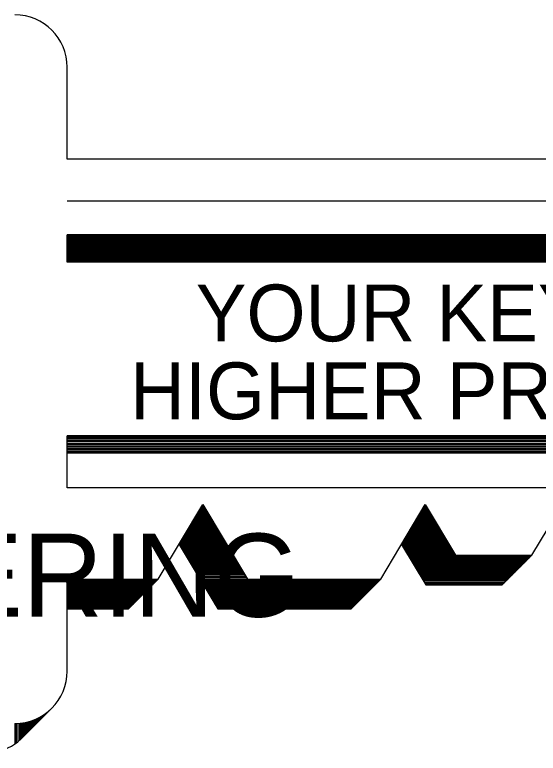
# Model space of a CAD drawing. Extents: x 44743.44 to 44747.1, y 44738.46 to 44741.29.
# Drawn here: x 44743.6828 to 44743.7348, y 44738.5496 to 44738.6229 of the extents above; entities that cross this region are included whole.
import ezdxf

# ---------------------------------------------------------------- set-up
doc = ezdxf.new("R2010")
doc.units = 0
for name, color, linetype in [('Level 1', 7, 'Continuous'), ('Level 10', 7, 'Continuous'), ('Level 2', 7, 'Continuous'), ('Level 7', 7, 'Continuous')]:
    doc.layers.add(name, color=color, linetype=linetype)

msp = doc.modelspace()

# ---------------------------------------------------------------- linework, layer by layer
at = {"layer": 'Level 1'}
msp.add_line((44743.6880458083, 44738.598307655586), (44743.6880458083, 44738.60102640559), dxfattribs=at)
at = {"layer": 'Level 10'}
msp.add_line((44743.7781708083, 44738.60438057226), (44743.6880458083, 44738.60438057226), dxfattribs=at)
at = {"layer": 'Level 2'}
for p, q in [((44743.782222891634, 44738.60102640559), (44743.6880458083, 44738.60102640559)), ((44743.782306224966, 44738.60096390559), (44743.6880458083, 44738.60096390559)), ((44743.78237914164, 44738.60090140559), (44743.6880458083, 44738.60090140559)), ((44743.78246247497, 44738.600828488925), (44743.6880458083, 44738.600828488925)), ((44743.78255622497, 44738.60075557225), (44743.6880458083, 44738.60075557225)), ((44743.7826395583, 44738.60068265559), (44743.6880458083, 44738.60068265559)), ((44743.782743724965, 44738.60059932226), (44743.6880458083, 44738.60059932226)), ((44743.7828270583, 44738.600526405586), (44743.6880458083, 44738.600526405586)), ((44743.78293122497, 44738.60044307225), (44743.6880458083, 44738.60044307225)), ((44743.783035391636, 44738.60035973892), (44743.6880458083, 44738.60035973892)), ((44743.78311872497, 44738.60028682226), (44743.6880458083, 44738.60028682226)), ((44743.78321247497, 44738.600203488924), (44743.6880458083, 44738.600203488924)), ((44743.7833270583, 44738.60012015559), (44743.6880458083, 44738.60012015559)), ((44743.78341039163, 44738.60004723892), (44743.6880458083, 44738.60004723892)), ((44743.783493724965, 44738.59997432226), (44743.6880458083, 44738.59997432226)), ((44743.783597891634, 44738.599890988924), (44743.6880458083, 44738.599890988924)), ((44743.7837020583, 44738.59980765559), (44743.6880458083, 44738.59980765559)), ((44743.783795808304, 44738.59972432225), (44743.6880458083, 44738.59972432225)), ((44743.783910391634, 44738.59963057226), (44743.6880458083, 44738.59963057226)), ((44743.784004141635, 44738.59955765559), (44743.6880458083, 44738.59955765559)), ((44743.784097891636, 44738.599474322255), (44743.6880458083, 44738.599474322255)), ((44743.784212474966, 44738.599380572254), (44743.6880458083, 44738.599380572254)), ((44743.784316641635, 44738.59929723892), (44743.6880458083, 44738.59929723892)), ((44743.7843895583, 44738.59923473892), (44743.6880458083, 44738.59923473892)), ((44743.78449372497, 44738.599151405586), (44743.6880458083, 44738.599151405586)), ((44743.78458747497, 44738.59906807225), (44743.6880458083, 44738.59906807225)), ((44743.78468122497, 44738.59899515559), (44743.6880458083, 44738.59899515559)), ((44743.7847645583, 44738.598922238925), (44743.6880458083, 44738.598922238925)), ((44743.784847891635, 44738.59885973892), (44743.6880458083, 44738.59885973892)), ((44743.784962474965, 44738.59876598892), (44743.6880458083, 44738.59876598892)), ((44743.78503539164, 44738.59870348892), (44743.6880458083, 44738.59870348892)), ((44743.78511872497, 44738.598630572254), (44743.6880458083, 44738.598630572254)), ((44743.78519164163, 44738.59856807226), (44743.6880458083, 44738.59856807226)), ((44743.785274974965, 44738.598505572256), (44743.6880458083, 44738.598505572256)), ((44743.78533747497, 44738.59845348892), (44743.6880458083, 44738.59845348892)), ((44743.78541039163, 44738.598390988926), (44743.6880458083, 44738.598390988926)), ((44743.78546247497, 44738.59834932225), (44743.6880458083, 44738.59834932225)), ((44743.7855145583, 44738.598307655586), (44743.6880458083, 44738.598307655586)), ((44743.790337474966, 44738.581099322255), (44743.6880458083, 44738.581099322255)), ((44743.6880458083, 44738.575932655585), (44743.6880458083, 44738.581099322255)), ((44743.7901708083, 44738.58096390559), (44743.6880458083, 44738.58096390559)), ((44743.78999372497, 44738.58081807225), (44743.6880458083, 44738.58081807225)), ((44743.7897958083, 44738.58065140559), (44743.6880458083, 44738.58065140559)), ((44743.78962914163, 44738.58051598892), (44743.6880458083, 44738.58051598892)), ((44743.78943122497, 44738.580349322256), (44743.6880458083, 44738.580349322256)), ((44743.78925414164, 44738.58020348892), (44743.6880458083, 44738.58020348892)), ((44743.789066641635, 44738.580047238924), (44743.6880458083, 44738.580047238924)), ((44743.788858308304, 44738.57988057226), (44743.6880458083, 44738.57988057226)), ((44743.7886708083, 44738.579724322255), (44743.6880458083, 44738.579724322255)), ((44743.78849372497, 44738.57957848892), (44743.6880458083, 44738.57957848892)), ((44743.78836872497, 44738.57947432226), (44743.6880458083, 44738.57947432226)), ((44743.78825414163, 44738.57938057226), (44743.6880458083, 44738.57938057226)), ((44743.78408747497, 44738.575932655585), (44743.6880458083, 44738.575932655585)), ((44743.701243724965, 44738.57382848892), (44743.701764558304, 44738.57382848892)), ((44743.7012958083, 44738.573911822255), (44743.70171247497, 44738.573911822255)), ((44743.701337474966, 44738.57399515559), (44743.7016708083, 44738.57399515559)), ((44743.7013895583, 44738.57407848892), (44743.70161872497, 44738.57407848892)), ((44743.701441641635, 44738.57416182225), (44743.701566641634, 44738.57416182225)), ((44743.723306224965, 44738.57382848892), (44743.723827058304, 44738.57382848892)), ((44743.7233583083, 44738.573911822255), (44743.72377497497, 44738.573911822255)), ((44743.723399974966, 44738.57399515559), (44743.7237333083, 44738.57399515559)), ((44743.72344164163, 44738.57405765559), (44743.72369164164, 44738.57405765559)), ((44743.7234833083, 44738.57412015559), (44743.72364997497, 44738.57412015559)), ((44743.7235145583, 44738.57418265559), (44743.723618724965, 44738.57418265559)), ((44743.700806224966, 44738.573078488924), (44743.70221247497, 44738.573078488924)), ((44743.70083747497, 44738.573161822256), (44743.70216039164, 44738.573161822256)), ((44743.7008895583, 44738.57324515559), (44743.70211872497, 44738.57324515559)), ((44743.70094164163, 44738.57332848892), (44743.702066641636, 44738.57332848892)), ((44743.70099372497, 44738.57341182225), (44743.7020145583, 44738.57341182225)), ((44743.7010458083, 44738.573495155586), (44743.70196247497, 44738.573495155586)), ((44743.70108747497, 44738.57357848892), (44743.70191039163, 44738.57357848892)), ((44743.7011395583, 44738.57366182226), (44743.701868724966, 44738.57366182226)), ((44743.70119164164, 44738.57374515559), (44743.70181664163, 44738.57374515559)), ((44743.722868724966, 44738.573078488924), (44743.72427497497, 44738.573078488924)), ((44743.72289997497, 44738.573161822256), (44743.72422289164, 44738.573161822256)), ((44743.7229520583, 44738.57324515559), (44743.72418122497, 44738.57324515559)), ((44743.72300414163, 44738.57332848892), (44743.724129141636, 44738.57332848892)), ((44743.72305622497, 44738.57341182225), (44743.7240770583, 44738.57341182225)), ((44743.7231083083, 44738.573495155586), (44743.72402497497, 44738.573495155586)), ((44743.72314997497, 44738.57357848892), (44743.72397289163, 44738.57357848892)), ((44743.7232020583, 44738.57366182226), (44743.723931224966, 44738.57366182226)), ((44743.72325414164, 44738.57374515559), (44743.72387914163, 44738.57374515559)), ((44743.700389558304, 44738.57241182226), (44743.702608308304, 44738.57241182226)), ((44743.70044164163, 44738.57249515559), (44743.70256664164, 44738.57249515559)), ((44743.700493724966, 44738.57257848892), (44743.7025145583, 44738.57257848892)), ((44743.7005458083, 44738.572661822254), (44743.70246247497, 44738.572661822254)), ((44743.700597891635, 44738.57274515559), (44743.702410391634, 44738.57274515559)), ((44743.70064997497, 44738.57282848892), (44743.70236872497, 44738.57282848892)), ((44743.700702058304, 44738.57291182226), (44743.70231664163, 44738.57291182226)), ((44743.70075414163, 44738.57299515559), (44743.7022645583, 44738.57299515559)), ((44743.722452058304, 44738.57241182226), (44743.724670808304, 44738.57241182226)), ((44743.72250414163, 44738.57249515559), (44743.72462914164, 44738.57249515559)), ((44743.722556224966, 44738.57257848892), (44743.7245770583, 44738.57257848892)), ((44743.7226083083, 44738.572661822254), (44743.72452497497, 44738.572661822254)), ((44743.722660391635, 44738.57274515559), (44743.724472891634, 44738.57274515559)), ((44743.72271247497, 44738.57282848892), (44743.72443122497, 44738.57282848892)), ((44743.722764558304, 44738.57291182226), (44743.72437914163, 44738.57291182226)), ((44743.72281664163, 44738.57299515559), (44743.7243270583, 44738.57299515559)), ((44743.699962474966, 44738.57166182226), (44743.70306664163, 44738.57166182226)), ((44743.69999372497, 44738.57174515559), (44743.7030145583, 44738.57174515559)), ((44743.7000458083, 44738.57182848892), (44743.70296247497, 44738.57182848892)), ((44743.70009789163, 44738.571911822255), (44743.702910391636, 44738.571911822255)), ((44743.7001395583, 44738.57199515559), (44743.7028583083, 44738.57199515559)), ((44743.700191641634, 44738.57207848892), (44743.702816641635, 44738.57207848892)), ((44743.70024372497, 44738.57216182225), (44743.7027645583, 44738.57216182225)), ((44743.7002958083, 44738.57224515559), (44743.702712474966, 44738.57224515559)), ((44743.70034789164, 44738.572328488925), (44743.70266039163, 44738.572328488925)), ((44743.722024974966, 44738.57166182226), (44743.72512914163, 44738.57166182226)), ((44743.72205622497, 44738.57174515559), (44743.7250770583, 44738.57174515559)), ((44743.7221083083, 44738.57182848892), (44743.72502497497, 44738.57182848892)), ((44743.72216039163, 44738.571911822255), (44743.724972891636, 44738.571911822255)), ((44743.7222020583, 44738.57199515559), (44743.7249208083, 44738.57199515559)), ((44743.722254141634, 44738.57207848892), (44743.724879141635, 44738.57207848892)), ((44743.72230622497, 44738.57216182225), (44743.7248270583, 44738.57216182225)), ((44743.7223583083, 44738.57224515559), (44743.724774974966, 44738.57224515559)), ((44743.72241039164, 44738.572328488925), (44743.72472289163, 44738.572328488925)), ((44743.69949372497, 44738.57091182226), (44743.7035145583, 44738.57091182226)), ((44743.699545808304, 44738.57099515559), (44743.703462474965, 44738.57099515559)), ((44743.69959789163, 44738.57107848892), (44743.70341039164, 44738.57107848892)), ((44743.699649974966, 44738.571161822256), (44743.7033583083, 44738.571161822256)), ((44743.6997020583, 44738.57124515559), (44743.70330622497, 44738.57124515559)), ((44743.699754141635, 44738.57132848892), (44743.7032645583, 44738.57132848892)), ((44743.69980622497, 44738.57141182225), (44743.70321247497, 44738.57141182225)), ((44743.699858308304, 44738.571495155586), (44743.70316039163, 44738.571495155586)), ((44743.69991039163, 44738.571578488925), (44743.7031083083, 44738.571578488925)), ((44743.72155622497, 44738.57091182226), (44743.7255770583, 44738.57091182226)), ((44743.721608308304, 44738.57099515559), (44743.725524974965, 44738.57099515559)), ((44743.72166039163, 44738.57107848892), (44743.72547289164, 44738.57107848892)), ((44743.721712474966, 44738.571161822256), (44743.7254208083, 44738.571161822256)), ((44743.7217645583, 44738.57124515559), (44743.72536872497, 44738.57124515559)), ((44743.721816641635, 44738.57132848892), (44743.7253270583, 44738.57132848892)), ((44743.72186872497, 44738.57141182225), (44743.72527497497, 44738.57141182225)), ((44743.721920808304, 44738.571495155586), (44743.72522289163, 44738.571495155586)), ((44743.72197289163, 44738.571578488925), (44743.7251708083, 44738.571578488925)), ((44743.69914997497, 44738.570328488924), (44743.70297289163, 44738.56393265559)), ((44743.69914997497, 44738.570328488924), (44743.7038583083, 44738.570328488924)), ((44743.69919164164, 44738.57041182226), (44743.70380622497, 44738.57041182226)), ((44743.6992020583, 44738.57024515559), (44743.70391039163, 44738.57024515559)), ((44743.699243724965, 44738.57049515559), (44743.703754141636, 44738.57049515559)), ((44743.69925414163, 44738.57016182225), (44743.70396247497, 44738.57016182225)), ((44743.6992958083, 44738.57057848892), (44743.70371247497, 44738.57057848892)), ((44743.699347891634, 44738.570661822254), (44743.703660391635, 44738.570661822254)), ((44743.6993895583, 44738.570745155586), (44743.7036083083, 44738.570745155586)), ((44743.699441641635, 44738.57082848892), (44743.703556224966, 44738.57082848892)), ((44743.72121247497, 44738.570328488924), (44743.723629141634, 44738.56630765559)), ((44743.72121247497, 44738.570328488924), (44743.7259208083, 44738.570328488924)), ((44743.72125414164, 44738.57041182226), (44743.72586872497, 44738.57041182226)), ((44743.7212645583, 44738.57024515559), (44743.72597289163, 44738.57024515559)), ((44743.721306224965, 44738.57049515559), (44743.725816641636, 44738.57049515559)), ((44743.72131664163, 44738.57016182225), (44743.72602497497, 44738.57016182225)), ((44743.7213583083, 44738.57057848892), (44743.72577497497, 44738.57057848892)), ((44743.721410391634, 44738.570661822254), (44743.725722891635, 44738.570661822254)), ((44743.7214520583, 44738.570745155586), (44743.7256708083, 44738.570745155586)), ((44743.721504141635, 44738.57082848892), (44743.725618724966, 44738.57082848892)), ((44743.6992958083, 44738.57007848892), (44743.70400414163, 44738.57007848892)), ((44743.699347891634, 44738.56999515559), (44743.70405622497, 44738.56999515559)), ((44743.69939997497, 44738.569911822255), (44743.704087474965, 44738.569911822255)), ((44743.6994520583, 44738.56982848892), (44743.7041395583, 44738.56982848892)), ((44743.69949372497, 44738.56974515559), (44743.704191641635, 44738.56974515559)), ((44743.699545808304, 44738.56966182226), (44743.70424372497, 44738.56966182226)), ((44743.69959789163, 44738.569578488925), (44743.704295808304, 44738.569578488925)), ((44743.699649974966, 44738.569495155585), (44743.70434789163, 44738.569495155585)), ((44743.7213583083, 44738.57007848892), (44743.72606664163, 44738.57007848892)), ((44743.721410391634, 44738.56999515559), (44743.72611872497, 44738.56999515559)), ((44743.72146247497, 44738.569911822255), (44743.726149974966, 44738.569911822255)), ((44743.7215145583, 44738.56982848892), (44743.7262020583, 44738.56982848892)), ((44743.72155622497, 44738.56974515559), (44743.726254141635, 44738.56974515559)), ((44743.721608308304, 44738.56966182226), (44743.72630622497, 44738.56966182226)), ((44743.72166039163, 44738.569578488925), (44743.726358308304, 44738.569578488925)), ((44743.721712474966, 44738.569495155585), (44743.72641039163, 44738.569495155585)), ((44743.6997020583, 44738.56941182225), (44743.704399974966, 44738.56941182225)), ((44743.69974372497, 44738.56932848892), (44743.7044520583, 44738.56932848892)), ((44743.6997958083, 44738.56924515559), (44743.704504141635, 44738.56924515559)), ((44743.699847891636, 44738.569161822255), (44743.70455622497, 44738.569161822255)), ((44743.6998895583, 44738.56909932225), (44743.704597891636, 44738.56909932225)), ((44743.69993122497, 44738.56901598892), (44743.7046395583, 44738.56901598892)), ((44743.6999833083, 44738.56893265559), (44743.70469164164, 44738.56893265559)), ((44743.70003539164, 44738.56883890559), (44743.70475414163, 44738.56883890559)), ((44743.70009789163, 44738.568734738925), (44743.704816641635, 44738.568734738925)), ((44743.7217645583, 44738.56941182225), (44743.726462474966, 44738.56941182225)), ((44743.72180622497, 44738.56932848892), (44743.7265145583, 44738.56932848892)), ((44743.7218583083, 44738.56924515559), (44743.726566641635, 44738.56924515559)), ((44743.721910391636, 44738.569161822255), (44743.72661872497, 44738.569161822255)), ((44743.7219520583, 44738.56909932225), (44743.726660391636, 44738.56909932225)), ((44743.72199372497, 44738.56901598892), (44743.7267020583, 44738.56901598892)), ((44743.7220458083, 44738.56893265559), (44743.72675414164, 44738.56893265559)), ((44743.72209789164, 44738.56883890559), (44743.72681664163, 44738.56883890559)), ((44743.72216039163, 44738.568734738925), (44743.726879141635, 44738.568734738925)), ((44743.72512914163, 44738.56915140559), (44743.73405622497, 44738.56915140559)), ((44743.72512914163, 44738.569057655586), (44743.733962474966, 44738.569057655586)), ((44743.72512914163, 44738.568963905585), (44743.733868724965, 44738.568963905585)), ((44743.72512914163, 44738.568849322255), (44743.733754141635, 44738.568849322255)), ((44743.72512914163, 44738.568734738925), (44743.733639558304, 44738.568734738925)), ((44743.731212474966, 44738.56630765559), (44743.734160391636, 44738.569255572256)), ((44743.700160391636, 44738.568640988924), (44743.70486872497, 44738.568640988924)), ((44743.70022289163, 44738.56852640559), (44743.704941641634, 44738.56852640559)), ((44743.700285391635, 44738.568422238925), (44743.70499372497, 44738.568422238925)), ((44743.70036872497, 44738.56829723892), (44743.7050770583, 44738.56829723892)), ((44743.70043122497, 44738.56818265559), (44743.705139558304, 44738.56818265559)), ((44743.700504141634, 44738.56805765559), (44743.70521247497, 44738.56805765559)), ((44743.722222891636, 44738.568640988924), (44743.72693122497, 44738.568640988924)), ((44743.722254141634, 44738.56859932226), (44743.73350414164, 44738.56859932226)), ((44743.7223270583, 44738.56847432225), (44743.73337914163, 44738.56847432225)), ((44743.72239997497, 44738.56834932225), (44743.73325414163, 44738.56834932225)), ((44743.72247289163, 44738.56823473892), (44743.7331395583, 44738.56823473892)), ((44743.7225458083, 44738.568109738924), (44743.733014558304, 44738.568109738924)), ((44743.72261872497, 44738.56798473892), (44743.7328895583, 44738.56798473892)), ((44743.7005770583, 44738.56793265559), (44743.7052958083, 44738.56793265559)), ((44743.7006395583, 44738.56782848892), (44743.7053583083, 44738.56782848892)), ((44743.700702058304, 44738.56772432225), (44743.7054208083, 44738.56772432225)), ((44743.70078539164, 44738.567599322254), (44743.70549372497, 44738.567599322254)), ((44743.70084789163, 44738.567484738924), (44743.705556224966, 44738.567484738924)), ((44743.7009208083, 44738.567359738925), (44743.70562914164, 44738.567359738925)), ((44743.72269164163, 44738.56785973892), (44743.7327645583, 44738.56785973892)), ((44743.722774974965, 44738.56773473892), (44743.7326395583, 44738.56773473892)), ((44743.72281664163, 44738.56765140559), (44743.73255622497, 44738.56765140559)), ((44743.722879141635, 44738.56755765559), (44743.73246247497, 44738.56755765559)), ((44743.7229520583, 44738.56743265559), (44743.73233747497, 44738.56743265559)), ((44743.72302497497, 44738.56730765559), (44743.73221247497, 44738.56730765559)), ((44743.6880458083, 44738.56677640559), (44743.69697289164, 44738.56677640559)), ((44743.6880458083, 44738.56668265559), (44743.69687914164, 44738.56668265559)), ((44743.6880458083, 44738.56658890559), (44743.696785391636, 44738.56658890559)), ((44743.69412914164, 44738.56393265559), (44743.6970770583, 44738.56688057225)), ((44743.701024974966, 44738.56719307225), (44743.7057333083, 44738.56719307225)), ((44743.7011083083, 44738.567057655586), (44743.70581664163, 44738.567057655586)), ((44743.70119164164, 44738.56691182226), (44743.705899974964, 44738.56691182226)), ((44743.70127497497, 44738.56677640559), (44743.7190458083, 44738.56677640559)), ((44743.701327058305, 44738.56668265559), (44743.7189520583, 44738.56668265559)), ((44743.7013895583, 44738.56658890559), (44743.718858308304, 44738.56658890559)), ((44743.7162020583, 44738.56393265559), (44743.71914997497, 44738.56688057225)), ((44743.723087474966, 44738.56720348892), (44743.7321083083, 44738.56720348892)), ((44743.7231708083, 44738.567068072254), (44743.73197289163, 44738.567068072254)), ((44743.72324372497, 44738.566943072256), (44743.731847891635, 44738.566943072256)), ((44743.7233270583, 44738.56681807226), (44743.731722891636, 44738.56681807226)), ((44743.7233895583, 44738.56670348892), (44743.7316083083, 44738.56670348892)), ((44743.7234833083, 44738.56655765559), (44743.73146247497, 44738.56655765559)), ((44743.6880458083, 44738.56647432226), (44743.6966708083, 44738.56647432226)), ((44743.6880458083, 44738.56635973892), (44743.69655622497, 44738.56635973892)), ((44743.6880458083, 44738.566224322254), (44743.6964208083, 44738.566224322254)), ((44743.6880458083, 44738.566099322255), (44743.6962958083, 44738.566099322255)), ((44743.6880458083, 44738.56597432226), (44743.6961708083, 44738.56597432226)), ((44743.6880458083, 44738.56585973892), (44743.696056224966, 44738.56585973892)), ((44743.7014520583, 44738.56647432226), (44743.71874372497, 44738.56647432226)), ((44743.70152497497, 44738.56635973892), (44743.71862914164, 44738.56635973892)), ((44743.7016083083, 44738.566224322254), (44743.71849372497, 44738.566224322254)), ((44743.70168122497, 44738.566099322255), (44743.71836872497, 44738.566099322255)), ((44743.701754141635, 44738.56597432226), (44743.718243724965, 44738.56597432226)), ((44743.70181664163, 44738.56585973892), (44743.718129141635, 44738.56585973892)), ((44743.72355622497, 44738.566432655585), (44743.731337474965, 44738.566432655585)), ((44743.723629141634, 44738.56630765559), (44743.731212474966, 44738.56630765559)), ((44743.6880458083, 44738.56573473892), (44743.69593122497, 44738.56573473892)), ((44743.6880458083, 44738.56560973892), (44743.69580622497, 44738.56560973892)), ((44743.6880458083, 44738.56548473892), (44743.69568122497, 44738.56548473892)), ((44743.6880458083, 44738.565359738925), (44743.69555622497, 44738.565359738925)), ((44743.6880458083, 44738.56527640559), (44743.69547289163, 44738.56527640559)), ((44743.6880458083, 44738.56518265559), (44743.69537914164, 44738.56518265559)), ((44743.6880458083, 44738.565057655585), (44743.69525414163, 44738.565057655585)), ((44743.70189997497, 44738.56573473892), (44743.718004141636, 44738.56573473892)), ((44743.701972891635, 44738.56560973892), (44743.71787914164, 44738.56560973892)), ((44743.7020458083, 44738.56548473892), (44743.71775414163, 44738.56548473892)), ((44743.70211872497, 44738.565359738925), (44743.71762914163, 44738.565359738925)), ((44743.702170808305, 44738.56527640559), (44743.7175458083, 44738.56527640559)), ((44743.70222289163, 44738.56518265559), (44743.7174520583, 44738.56518265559)), ((44743.7022958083, 44738.565057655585), (44743.7173270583, 44738.565057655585)), ((44743.6880458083, 44738.56493265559), (44743.69512914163, 44738.56493265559)), ((44743.6880458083, 44738.564828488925), (44743.695024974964, 44738.564828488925)), ((44743.6880458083, 44738.56469307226), (44743.694889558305, 44738.56469307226)), ((44743.6880458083, 44738.56456807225), (44743.6947645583, 44738.56456807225)), ((44743.6880458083, 44738.56444307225), (44743.6946395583, 44738.56444307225)), ((44743.6880458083, 44738.56432848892), (44743.69452497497, 44738.56432848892)), ((44743.702379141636, 44738.56493265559), (44743.7172020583, 44738.56493265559)), ((44743.70244164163, 44738.564828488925), (44743.71709789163, 44738.564828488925)), ((44743.7025145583, 44738.56469307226), (44743.716962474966, 44738.56469307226)), ((44743.702597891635, 44738.56456807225), (44743.71683747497, 44738.56456807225)), ((44743.7026708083, 44738.56444307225), (44743.71671247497, 44738.56444307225)), ((44743.7027333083, 44738.56432848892), (44743.71659789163, 44738.56432848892)), ((44743.6880458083, 44738.56418265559), (44743.694379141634, 44738.56418265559)), ((44743.6880458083, 44738.56405765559), (44743.694254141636, 44738.56405765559)), ((44743.6880458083, 44738.56393265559), (44743.69412914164, 44738.56393265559)), ((44743.7028270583, 44738.56418265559), (44743.7164520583, 44738.56418265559)), ((44743.70289997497, 44738.56405765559), (44743.716327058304, 44738.56405765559)), ((44743.70297289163, 44738.56393265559), (44743.7162020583, 44738.56393265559)), ((44743.6835770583, 44738.551130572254), (44743.68652497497, 44738.55407848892)), ((44743.6855770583, 44738.553130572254), (44743.6855770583, 44738.553338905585)), ((44743.68568122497, 44738.55323473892), (44743.68568122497, 44738.55340140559)), ((44743.68577497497, 44738.553328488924), (44743.68577497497, 44738.55346390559)), ((44743.68586872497, 44738.553422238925), (44743.68586872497, 44738.55352640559)), ((44743.68596247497, 44738.55351598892), (44743.68596247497, 44738.55359932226)), ((44743.6833270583, 44738.550901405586), (44743.6833270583, 44738.552578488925)), ((44743.68347289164, 44738.55103682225), (44743.68347289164, 44738.552599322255)), ((44743.683597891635, 44738.55115140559), (44743.683597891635, 44738.55260973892)), ((44743.6837333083, 44738.55128682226), (44743.6837333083, 44738.55263057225)), ((44743.68383747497, 44738.55139098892), (44743.68383747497, 44738.55265140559)), ((44743.68396247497, 44738.551515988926), (44743.68396247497, 44738.55268265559)), ((44743.68406664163, 44738.55162015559), (44743.68406664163, 44738.552703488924)), ((44743.68418122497, 44738.551734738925), (44743.68418122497, 44738.55273473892)), ((44743.68430622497, 44738.551859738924), (44743.68430622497, 44738.55276598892)), ((44743.6843895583, 44738.551943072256), (44743.6843895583, 44738.552797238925)), ((44743.68449372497, 44738.552047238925), (44743.68449372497, 44738.55282848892)), ((44743.68458747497, 44738.55214098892), (44743.68458747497, 44738.55285973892)), ((44743.68469164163, 44738.55224515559), (44743.68469164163, 44738.55290140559)), ((44743.684754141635, 44738.55230765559), (44743.684754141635, 44738.55292223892)), ((44743.684879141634, 44738.55243265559), (44743.684879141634, 44738.55297432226)), ((44743.684972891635, 44738.55252640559), (44743.684972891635, 44738.553015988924)), ((44743.685077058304, 44738.55263057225), (44743.685077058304, 44738.55306807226)), ((44743.685191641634, 44738.55274515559), (44743.685191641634, 44738.553120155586)), ((44743.685285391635, 44738.55283890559), (44743.685285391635, 44738.55317223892)), ((44743.685379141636, 44738.55293265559), (44743.685379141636, 44738.553224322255)), ((44743.68547289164, 44738.553026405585), (44743.68547289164, 44738.55327640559)), ((44743.6828895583, 44738.55055765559), (44743.6828895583, 44738.55255765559)), ((44743.68302497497, 44738.55066182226), (44743.68302497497, 44738.55255765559)), ((44743.683170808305, 44738.55077640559), (44743.683170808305, 44738.55255765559))]:
    msp.add_line(p, q, dxfattribs=at)
msp.add_arc((44743.67989235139, 44738.554814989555), 0.005208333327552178, 270, 338.59208611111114, dxfattribs=at)
at = {"layer": 'Level 7'}
for p, q in [((44743.6880458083, 44738.608547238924), (44743.6880458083, 44738.61766182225)), ((44743.773129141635, 44738.608547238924), (44743.6880458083, 44738.608547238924)), ((44743.6970770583, 44738.56688057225), (44743.70150414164, 44738.57426598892)), ((44743.70150414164, 44738.57426598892), (44743.7059208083, 44738.56688057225)), ((44743.71914997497, 44738.56688057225), (44743.72356664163, 44738.57426598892)), ((44743.72356664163, 44738.57426598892), (44743.7265770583, 44738.569255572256)), ((44743.734160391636, 44738.569255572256), (44743.73716039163, 44738.57426598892)), ((44743.7265770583, 44738.569255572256), (44743.734160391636, 44738.569255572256)), ((44743.6880458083, 44738.557765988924), (44743.6880458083, 44738.56688057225)), ((44743.6880458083, 44738.56688057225), (44743.6970770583, 44738.56688057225)), ((44743.7059208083, 44738.56688057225), (44743.71914997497, 44738.56688057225))]:
    msp.add_line(p, q, dxfattribs=at)
for centre, start, end in [((44743.68284026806, 44738.61765873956), 0, 90), ((44743.68284026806, 44738.557762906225), 270, 0)]:
    msp.add_arc(centre, 0.005208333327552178, start, end, dxfattribs=at)

# ---------------------------------------------------------------- texts
at = {"layer": 'Level 2'}
for s, height, p in [('YOUR KEY TO', 0.005640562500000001, (44743.7007958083, 44738.59046390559)), ('HIGHER PROFITS', 0.005640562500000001, (44743.694274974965, 44738.58273473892)), ('ENGINEERING', 0.008249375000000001, (44743.633972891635, 44738.563140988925))]:
    msp.add_text(s, height=height, dxfattribs=at).set_placement(p)

doc.saveas('drawing.dxf')
